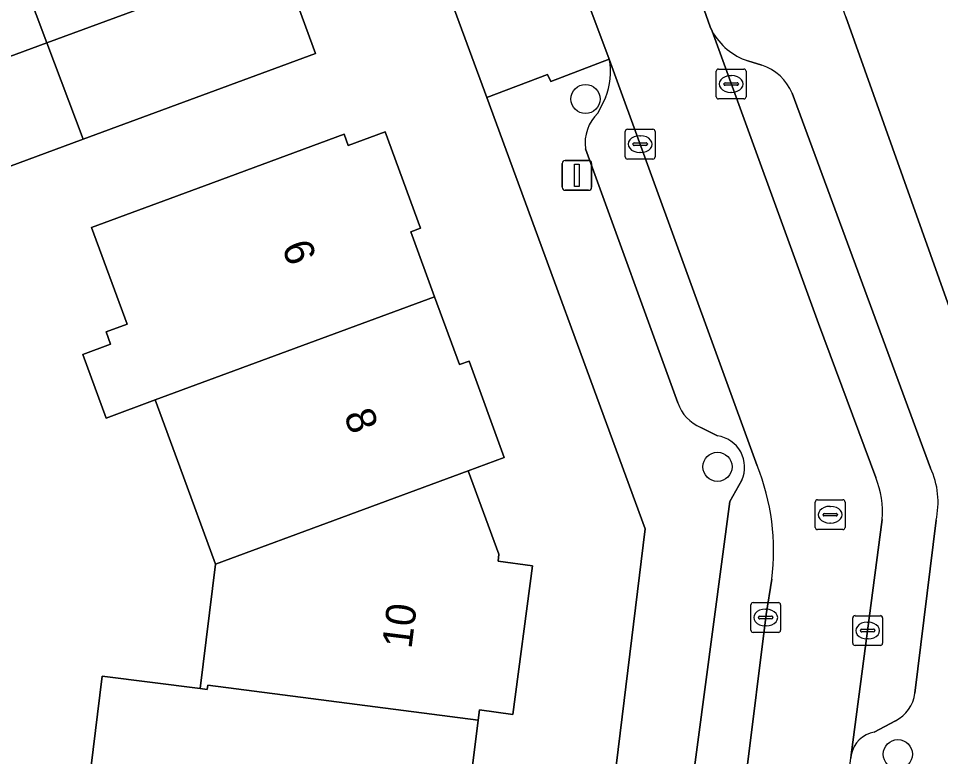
# Model space of a CAD drawing. Extents: x 161258 to 161838, y 380833 to 381727.
# Drawn here: x 161604.79 to 161635.74, y 381408.58 to 381433.33 of the extents above; entities that cross this region are included whole.
import ezdxf

# ---------------------------------------------------------------- set-up
doc = ezdxf.new("R2010")
doc.units = 0
for name, color, linetype in [('IMGEO_Boom', 7, 'Continuous'), ('IMGEO_Erf', 7, 'Continuous'), ('IMGEO_Kolk', 7, 'Continuous'), ('IMGEO_Lichtmast', 7, 'Continuous'), ('IMGEO_Pand', 7, 'Continuous'), ('IMGEO_Pand_nummerreeks', 7, 'Continuous'), ('IMGEO_Parkeervlak_open', 7, 'Continuous'), ('IMGEO_Rijbaan_lokaal_open', 7, 'Continuous'), ('IMGEO_Rioolput', 7, 'Continuous'), ('IMGEO_Voetpad_open', 7, 'Continuous')]:
    doc.layers.add(name, color=color, linetype=linetype)

msp = doc.modelspace()

# ---------------------------------------------------------------- linework, layer by layer
at = {"layer": 'IMGEO_Boom'}
for centre in [(161623.822, 381430.63), (161628.251, 381418.294), (161634.307, 381408.655)]:
    msp.add_circle(centre, 0.489, dxfattribs=at)
at = {"layer": 'IMGEO_Erf'}
for points in [[(161625.828, 381416.218), (161620.508, 381430.682), (161617.919, 381437.722), (161610.973, 381456.609), (161591.531, 381449.546), (161590.178, 381449.054), (161586.626, 381447.764), (161584.326, 381446.929), (161582.834, 381446.387), (161582.376, 381446.221), (161568.663, 381441.239)], [(161602.965, 381439.859), (161605.743, 381432.515), (161613.568, 381435.402), (161614.764, 381432.159), (161606.966, 381429.283), (161604.141, 381428.241), (161602.945, 381431.483), (161601.457, 381430.934), (161599.115, 381436.986)], [(161632.557, 381433.385), (161638.239, 381417.444), (161637.547, 381412.742), (161634.273, 381385.117), (161633.778, 381381.183), (161631.183, 381360.562), (161646.49, 381358.638), (161649.876, 381358.212), (161669.686, 381355.721)], [(161607.215, 381408.173), (161607.601, 381411.267), (161610.885, 381410.86), (161611.402, 381415.027), (161610.2, 381418.293), (161609.375, 381420.535), (161607.734, 381419.929), (161606.945, 381422.066), (161607.88, 381422.411), (161607.73, 381422.818), (161608.439, 381423.08), (161607.245, 381426.324), (161611.031, 381427.715), (161615.722, 381429.445), (161615.858, 381429.075), (161617.095, 381429.532), (161618.288, 381426.298), (161617.959, 381426.177), (161618.756, 381423.997), (161619.588, 381421.723), (161619.914, 381421.837), (161621.096, 381418.604), (161619.886, 381418.157), (161620.917, 381415.363), (161620.888, 381415.131), (161622.04, 381414.971), (161621.383, 381409.991), (161620.266, 381410.138), (161620.224, 381409.8), (161619.842, 381406.729)], [(161568.046, 381368.678), (161594.615, 381365.296), (161601.597, 381364.408), (161619.194, 381362.168), (161620.757, 381374.9), (161621.814, 381383.511), (161622.597, 381389.891), (161625.828, 381416.218)]]:
    msp.add_lwpolyline(points, dxfattribs=at)
at = {"layer": 'IMGEO_Kolk'}
for p, q in [((161628.21, 381430.707), (161628.21, 381431.559)), ((161628.285, 381431.633), (161629.137, 381431.633)), ((161629.211, 381431.559), (161629.211, 381430.707)), ((161628.698, 381431.413), (161628.723, 381431.413)), ((161628.469, 381431.127), (161628.469, 381431.139)), ((161628.907, 381431.09), (161628.509, 381431.09)), ((161628.512, 381431.176), (161628.91, 381431.176)), ((161628.953, 381431.139), (161628.953, 381431.127)), ((161629.137, 381430.633), (161628.285, 381430.633)), ((161628.721, 381430.853), (161628.696, 381430.853)), ((161625.156, 381428.69), (161625.156, 381429.542)), ((161625.231, 381429.616), (161626.083, 381429.616)), ((161625.644, 381429.396), (161625.669, 381429.396)), ((161626.157, 381429.542), (161626.157, 381428.69)), ((161625.415, 381429.11), (161625.415, 381429.122)), ((161625.853, 381429.073), (161625.455, 381429.073)), ((161625.458, 381429.159), (161625.856, 381429.159)), ((161625.899, 381429.122), (161625.899, 381429.11)), ((161625.667, 381428.836), (161625.642, 381428.836)), ((161626.083, 381428.616), (161625.231, 381428.616)), ((161629.37, 381412.812), (161629.37, 381413.664)), ((161629.445, 381413.738), (161630.297, 381413.738)), ((161630.371, 381413.664), (161630.371, 381412.812)), ((161629.672, 381413.281), (161630.07, 381413.281)), ((161629.858, 381413.518), (161629.883, 381413.518)), ((161632.868, 381413.301), (161633.72, 381413.301)), ((161629.629, 381413.232), (161629.629, 381413.244)), ((161630.067, 381413.195), (161629.669, 381413.195)), ((161630.113, 381413.244), (161630.113, 381413.232)), ((161632.793, 381412.375), (161632.793, 381413.227)), ((161633.281, 381413.081), (161633.306, 381413.081)), ((161633.794, 381413.227), (161633.794, 381412.375)), ((161630.297, 381412.738), (161629.445, 381412.738)), ((161629.881, 381412.958), (161629.856, 381412.958)), ((161633.052, 381412.795), (161633.052, 381412.807)), ((161633.49, 381412.758), (161633.092, 381412.758)), ((161633.095, 381412.844), (161633.493, 381412.844)), ((161633.536, 381412.807), (161633.536, 381412.795)), ((161633.304, 381412.521), (161633.279, 381412.521)), ((161633.72, 381412.301), (161632.868, 381412.301))]:
    msp.add_line(p, q, dxfattribs=at)
for points in [[(161628.21, 381430.707), (161628.21, 381431.559)], [(161628.285, 381431.633), (161629.137, 381431.633)], [(161629.211, 381431.559), (161629.211, 381430.707)], [(161629.137, 381430.633), (161628.285, 381430.633)], [(161625.156, 381428.69), (161625.156, 381429.542)], [(161625.231, 381429.616), (161626.083, 381429.616)], [(161626.157, 381429.542), (161626.157, 381428.69)], [(161626.083, 381428.616), (161625.231, 381428.616)], [(161629.37, 381412.812), (161629.37, 381413.664)], [(161629.445, 381413.738), (161630.297, 381413.738)], [(161630.371, 381413.664), (161630.371, 381412.812)], [(161632.868, 381413.301), (161633.72, 381413.301)], [(161632.793, 381412.375), (161632.793, 381413.227)], [(161633.794, 381413.227), (161633.794, 381412.375)], [(161630.297, 381412.738), (161629.445, 381412.738)], [(161633.72, 381412.301), (161632.868, 381412.301)]]:
    msp.add_lwpolyline(points, dxfattribs=at)
for centre, radius, start, end in [((161628.287, 381431.557), 0.0765, 91.552, 178.448), ((161628.287, 381431.557), 0.0765, 91.552, 178.448), ((161629.135, 381431.557), 0.0765, 1.552, 88.448), ((161629.135, 381431.557), 0.0765, 1.552, 88.448), ((161628.509, 381431.136), 0.0403, 85.8775, 175.7526), ((161628.506, 381431.126), 0.0366, 178.938, 274.7102), ((161628.91, 381431.133), 0.043, 264.8664, 352.4533), ((161628.914, 381431.138), 0.0386, 1.7309, 96.639), ((161628.287, 381430.709), 0.0765, 181.552, 268.448), ((161628.287, 381430.709), 0.0765, 181.552, 268.448), ((161629.135, 381430.709), 0.0765, 271.552, 358.448), ((161629.135, 381430.709), 0.0765, 271.552, 358.448), ((161625.233, 381429.54), 0.0765, 91.552, 178.448), ((161625.233, 381429.54), 0.0765, 91.552, 178.448), ((161626.081, 381429.54), 0.0765, 1.552, 88.448), ((161626.081, 381429.54), 0.0765, 1.552, 88.448), ((161625.455, 381429.119), 0.0403, 85.8775, 175.7526), ((161625.452, 381429.109), 0.0366, 178.938, 274.7102), ((161625.856, 381429.116), 0.043, 264.8664, 352.4533), ((161625.86, 381429.121), 0.0386, 1.7309, 96.639), ((161625.233, 381428.692), 0.0765, 181.552, 268.448), ((161625.233, 381428.692), 0.0765, 181.552, 268.448), ((161626.081, 381428.692), 0.0765, 271.552, 358.448), ((161626.081, 381428.692), 0.0765, 271.552, 358.448), ((161629.447, 381413.662), 0.0765, 91.552, 178.448), ((161629.447, 381413.662), 0.0765, 91.552, 178.448), ((161630.295, 381413.662), 0.0765, 1.552, 88.448), ((161630.295, 381413.662), 0.0765, 1.552, 88.448), ((161629.669, 381413.241), 0.0403, 85.8775, 175.7526), ((161630.074, 381413.243), 0.0386, 1.7309, 96.639), ((161632.87, 381413.225), 0.0765, 91.552, 178.448), ((161632.87, 381413.225), 0.0765, 91.552, 178.448), ((161633.718, 381413.225), 0.0765, 1.552, 88.448), ((161633.718, 381413.225), 0.0765, 1.552, 88.448), ((161629.666, 381413.231), 0.0366, 178.938, 274.7102), ((161630.07, 381413.238), 0.043, 264.8664, 352.4533), ((161629.447, 381412.814), 0.0765, 181.552, 268.448), ((161629.447, 381412.814), 0.0765, 181.552, 268.448), ((161630.295, 381412.814), 0.0765, 271.552, 358.448), ((161630.295, 381412.814), 0.0765, 271.552, 358.448), ((161633.092, 381412.804), 0.0403, 85.8775, 175.7526), ((161633.089, 381412.794), 0.0366, 178.938, 274.7102), ((161633.493, 381412.801), 0.043, 264.8664, 352.4533), ((161633.497, 381412.806), 0.0386, 1.7309, 96.639), ((161632.87, 381412.377), 0.0765, 181.552, 268.448), ((161632.87, 381412.377), 0.0765, 181.552, 268.448), ((161633.718, 381412.377), 0.0765, 271.552, 358.448), ((161633.718, 381412.377), 0.0765, 271.552, 358.448)]:
    msp.add_arc(centre, radius, start, end, dxfattribs=at)
for centre, major_axis, ratio, start_param, end_param in [((161628.697, 381431.133), (-0.387, 0.002), 0.722429, 4.712389, 7.853982), ((161628.722, 381431.133), (-0.39, 0.002), 0.717154, 1.570796, 4.712389), ((161625.643, 381429.116), (-0.387, 0.002), 0.722429, 4.712389, 7.853982), ((161625.668, 381429.116), (-0.39, 0.002), 0.717154, 1.570796, 4.712389), ((161629.857, 381413.238), (-0.387, 0.002), 0.722429, 4.712389, 7.853982), ((161629.882, 381413.238), (-0.39, 0.002), 0.717154, 1.570796, 4.712389), ((161633.28, 381412.801), (-0.387, 0.002), 0.722429, 4.712389, 7.853982), ((161633.305, 381412.801), (-0.39, 0.002), 0.717154, 1.570796, 4.712389)]:
    msp.add_ellipse(centre, major_axis=major_axis, ratio=ratio, start_param=start_param, end_param=end_param, dxfattribs=at)
at = {"layer": 'IMGEO_Lichtmast'}
for p, q in [((161623.037, 381427.669), (161623.037, 381428.469)), ((161623.037, 381428.469), (161623.037, 381427.669)), ((161623.137, 381428.569), (161623.927, 381428.569)), ((161623.927, 381428.569), (161623.137, 381428.569)), ((161624.027, 381428.469), (161624.027, 381427.669)), ((161624.027, 381427.669), (161624.027, 381428.469)), ((161623.927, 381427.569), (161623.137, 381427.569)), ((161623.137, 381427.569), (161623.927, 381427.569))]:
    msp.add_line(p, q, dxfattribs=at)
msp.add_lwpolyline([(161623.457, 381428.444), (161623.607, 381428.444), (161623.607, 381427.694), (161623.457, 381427.694), (161623.457, 381428.444)], dxfattribs=at)
for centre, start, end in [((161623.137, 381428.469), 90, 180), ((161623.137, 381428.469), 90, 180), ((161623.927, 381428.469), 0, 90), ((161623.927, 381428.469), 360, 90), ((161623.137, 381427.669), 180, 270), ((161623.137, 381427.669), 180, 270), ((161623.927, 381427.669), 270, 0), ((161623.927, 381427.669), 270, 0)]:
    msp.add_arc(centre, 0.1, start, end, dxfattribs=at)
at = {"layer": 'IMGEO_Pand'}
for points in [[(161599.981, 381447.747), (161599.739, 381447.659), (161599.852, 381447.348), (161597.142, 381446.364), (161596.986, 381446.794), (161593.906, 381445.675), (161594.08, 381445.198), (161592.983, 381444.799), (161594.322, 381441.112), (161593.577, 381440.841), (161592.386, 381440.394), (161594.67, 381434.649), (161595.097, 381434.811), (161594.88, 381435.371), (161599.115, 381436.986), (161601.457, 381430.934), (161602.945, 381431.483), (161605.743, 381432.515), (161602.965, 381439.859)], [(161605.743, 381432.515), (161606.966, 381429.283), (161614.764, 381432.159), (161613.568, 381435.402)], [(161605.743, 381432.515), (161602.945, 381431.483), (161604.141, 381428.241), (161606.966, 381429.283)], [(161618.756, 381423.997), (161617.959, 381426.177), (161618.288, 381426.298), (161617.095, 381429.532), (161615.858, 381429.075), (161615.722, 381429.445), (161611.031, 381427.715), (161607.245, 381426.324), (161608.439, 381423.08), (161607.73, 381422.818), (161607.88, 381422.411), (161606.945, 381422.066), (161607.734, 381419.929), (161609.375, 381420.535)], [(161619.914, 381421.837), (161619.588, 381421.723), (161618.756, 381423.997), (161609.375, 381420.535), (161610.2, 381418.293), (161611.402, 381415.027), (161619.886, 381418.157), (161621.096, 381418.604)], [(161622.04, 381414.971), (161620.888, 381415.131), (161620.917, 381415.363), (161619.886, 381418.157), (161611.402, 381415.027), (161610.885, 381410.86), (161611.123, 381410.83), (161611.14, 381410.972), (161620.224, 381409.8), (161620.266, 381410.138), (161621.383, 381409.991)], [(161620.224, 381409.8), (161611.14, 381410.972), (161611.123, 381410.83), (161610.885, 381410.86), (161607.601, 381411.267), (161607.215, 381408.173), (161609.689, 381407.854), (161609.206, 381403.969), (161619.281, 381402.669), (161619.387, 381403.518), (161620.449, 381403.966), (161620.711, 381406.072), (161619.842, 381406.729)]]:
    msp.add_lwpolyline(points, close=True, dxfattribs=at)
at = {"layer": 'IMGEO_Parkeervlak_open'}
for points in [[(161628.071, 381432.908), (161631.642, 381423.104), (161633.562, 381417.932)], [(161629.58, 381418.332), (161624.621, 381431.971)], [(161629.742, 381431.766), (161629.273, 381431.907)], [(161624.496, 381430.667), (161624.24, 381430.16)], [(161635.402, 381418.251), (161630.754, 381430.823)], [(161623.816, 381428.956), (161626.919, 381420.439)], [(161627.69, 381419.611), (161628.247, 381419.33)], [(161629.067, 381417.842), (161628.67, 381417.132), (161626.501, 381400.815)], [(161633.782, 381416.523), (161632.744, 381408.636)], [(161634.878, 381410.7), (161635.586, 381416.499)], [(161627.951, 381398.186), (161629.229, 381408.041), (161629.886, 381413.343), (161630.074, 381414.521)], [(161633.515, 381409.397), (161634.227, 381409.775)]]:
    msp.add_lwpolyline(points, dxfattribs=at)
for centre, radius, start, end in [((161629.94, 381433.93), 2.13, 208.6722, 251.7542), ((161622.38, 381431.528), 2.284, 337.861, 11.1879), ((161629.22, 381430.191), 1.659, 22.38, 71.6627), ((161625.225, 381429.137), 1.42, 133.8951, 187.3045), ((161628.219, 381420.877), 1.372, 198.6057, 247.3111), ((161628.104, 381418.281), 1.059, 335.4871, 82.229), ((161622.538, 381415.482), 7.597, 352.7345, 22.0371), ((161632.957, 381417.109), 2.699, 346.9493, 25.0415), ((161630.83, 381416.784), 2.964, 354.9531, 22.7958), ((161633.669, 381410.859), 1.219, 297.2181, 352.5074), ((161633.674, 381408.465), 0.946, 99.6962, 169.5558)]:
    msp.add_arc(centre, radius, start, end, dxfattribs=at)
at = {"layer": 'IMGEO_Rijbaan_lokaal_open'}
for points in [[(161633.562, 381417.932), (161631.642, 381423.104), (161628.071, 381432.908), (161628.007, 381433.055), (161627.799, 381433.622), (161626.464, 381437.265), (161626.262, 381437.814), (161620.858, 381452.321), (161619.845, 381455.009), (161618.312, 381459.03)], [(161614.862, 381457.971), (161617.533, 381450.961), (161621.851, 381439.353), (161621.897, 381439.229), (161624.621, 381431.971), (161629.58, 381418.332)], [(161631.028, 381395.148), (161632.729, 381408.516), (161632.744, 381408.636), (161633.782, 381416.523)], [(161630.074, 381414.521), (161629.886, 381413.343), (161629.229, 381408.041), (161627.951, 381398.186), (161627.937, 381398.058), (161626.958, 381389.351), (161626.112, 381382.98), (161626.09, 381382.805), (161624.952, 381373.802), (161623.53, 381361.715), (161623.507, 381361.52), (161626.762, 381361.028), (161626.779, 381361.172), (161626.812, 381361.453), (161627.856, 381370.215), (161629.358, 381381.739), (161629.854, 381385.901), (161630.024, 381387.329), (161631.028, 381395.148)]]:
    msp.add_lwpolyline(points, dxfattribs=at)
for centre, radius, start, end in [((161622.538, 381415.482), 7.597, 352.7345, 22.0371), ((161630.83, 381416.784), 2.964, 354.9531, 22.7958)]:
    msp.add_arc(centre, radius, start, end, dxfattribs=at)
at = {"layer": 'IMGEO_Rioolput'}
for p, q in [((161631.535, 381416.261), (161631.535, 381417.113)), ((161631.61, 381417.187), (161632.462, 381417.187)), ((161632.536, 381417.113), (161632.536, 381416.261)), ((161631.794, 381416.681), (161631.794, 381416.693)), ((161631.837, 381416.73), (161632.235, 381416.73)), ((161632.023, 381416.967), (161632.048, 381416.967)), ((161632.278, 381416.693), (161632.278, 381416.681)), ((161632.232, 381416.644), (161631.834, 381416.644)), ((161632.046, 381416.407), (161632.021, 381416.407)), ((161632.462, 381416.187), (161631.61, 381416.187))]:
    msp.add_line(p, q, dxfattribs=at)
for points in [[(161631.535, 381416.261), (161631.535, 381417.113)], [(161631.61, 381417.187), (161632.462, 381417.187)], [(161632.536, 381417.113), (161632.536, 381416.261)], [(161632.462, 381416.187), (161631.61, 381416.187)]]:
    msp.add_lwpolyline(points, dxfattribs=at)
for centre, radius, start, end in [((161631.612, 381417.111), 0.0765, 91.552, 178.448), ((161631.612, 381417.111), 0.0765, 91.552, 178.448), ((161632.46, 381417.111), 0.0765, 1.552, 88.448), ((161632.46, 381417.111), 0.0765, 1.552, 88.448), ((161631.834, 381416.69), 0.0403, 85.8775, 175.7526), ((161632.239, 381416.692), 0.0386, 1.7309, 96.639), ((161631.831, 381416.68), 0.0366, 178.938, 274.7102), ((161632.235, 381416.687), 0.043, 264.8664, 352.4533), ((161631.612, 381416.263), 0.0765, 181.552, 268.448), ((161631.612, 381416.263), 0.0765, 181.552, 268.448), ((161632.46, 381416.263), 0.0765, 271.552, 358.448), ((161632.46, 381416.263), 0.0765, 271.552, 358.448)]:
    msp.add_arc(centre, radius, start, end, dxfattribs=at)
for centre, major_axis, ratio, start_param, end_param in [((161632.022, 381416.687), (-0.387, 0.002), 0.722429, 4.712389, 7.853982), ((161632.047, 381416.687), (-0.39, 0.002), 0.717154, 1.570796, 4.712389)]:
    msp.add_ellipse(centre, major_axis=major_axis, ratio=ratio, start_param=start_param, end_param=end_param, dxfattribs=at)
at = {"layer": 'IMGEO_Voetpad_open'}
msp.add_lwpolyline([(161621.897, 381439.229), (161617.919, 381437.722), (161620.508, 381430.682), (161622.544, 381431.448), (161622.657, 381431.22), (161624.621, 381431.971)], close=True, dxfattribs=at)
for points in [[(161637.547, 381412.742), (161638.239, 381417.444), (161632.557, 381433.385), (161631.8, 381435.51), (161631.7, 381435.792), (161629.12, 381434.891), (161629.396, 381434.192), (161627.799, 381433.622), (161628.007, 381433.055), (161628.071, 381432.908)], [(161624.621, 381431.971), (161622.657, 381431.22), (161622.544, 381431.448), (161620.508, 381430.682), (161625.828, 381416.218), (161622.597, 381389.891), (161626.958, 381389.351)], [(161629.273, 381431.907), (161629.742, 381431.766)], [(161624.24, 381430.16), (161624.496, 381430.667)], [(161630.754, 381430.823), (161635.402, 381418.251)], [(161626.919, 381420.439), (161623.816, 381428.956)], [(161628.247, 381419.33), (161627.69, 381419.611)], [(161626.501, 381400.815), (161628.67, 381417.132), (161629.067, 381417.842)], [(161635.586, 381416.499), (161634.878, 381410.7)], [(161634.227, 381409.775), (161633.515, 381409.397)], [(161632.744, 381408.636), (161632.729, 381408.516)]]:
    msp.add_lwpolyline(points, dxfattribs=at)
for centre, radius, start, end in [((161629.94, 381433.93), 2.13, 208.6722, 251.7542), ((161622.38, 381431.528), 2.284, 337.861, 11.1879), ((161629.22, 381430.191), 1.659, 22.38, 71.6627), ((161625.225, 381429.137), 1.42, 133.8951, 187.3045), ((161628.219, 381420.877), 1.372, 198.6057, 247.3111), ((161628.104, 381418.281), 1.059, 335.4871, 82.229), ((161632.957, 381417.109), 2.699, 346.9493, 25.0415), ((161633.669, 381410.859), 1.219, 297.2181, 352.5074), ((161633.674, 381408.465), 0.946, 99.6962, 169.5558)]:
    msp.add_arc(centre, radius, start, end, dxfattribs=at)

# ---------------------------------------------------------------- texts
at = {"layer": 'IMGEO_Pand_nummerreeks'}
for s, rotation, p in [('6', 290.2496, (161613.616, 381425.678)), ('8', 290.2481, (161615.7, 381420.03)), ('10', 82.9013, (161617.979, 381412.166))]:
    msp.add_text(s, height=1, rotation=rotation, dxfattribs=at).set_placement(p)

doc.saveas('drawing.dxf')
